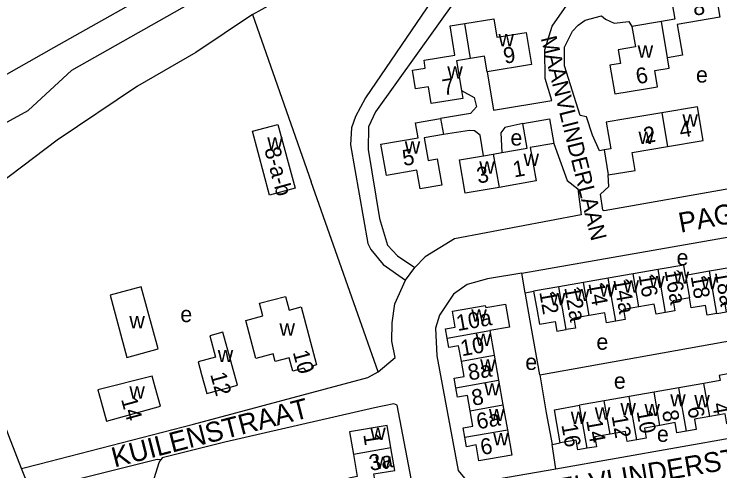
# Model space of a CAD drawing. Extents: x 162883 to 165538, y 383986 to 385172.
# Drawn here: x 163773.3 to 163949.9, y 384629.9 to 384744.4 of the extents above; entities that cross this region are included whole.
import ezdxf

# ---------------------------------------------------------------- set-up
doc = ezdxf.new("R2010")
doc.units = 0
for name, color, linetype in [('BLT_Basislijn', 7, 'Continuous'), ('BLT_Bebouwing', 7, 'Continuous'), ('BLT_Centroide', 7, 'Continuous'), ('BLT_Huisnummer', 7, 'Continuous'), ('BLT_Huisnummer_ tussenligend', 7, 'Continuous'), ('BLT_Huisnummer_reeks', 7, 'Continuous'), ('BLT_Onderverdeling_panden', 7, 'Continuous'), ('BLT_Straatnaam', 7, 'Continuous'), ('BLT_Straatnaam_verkleind', 7, 'Continuous')]:
    doc.layers.add(name, color=color, linetype=linetype)

msp = doc.modelspace()

# ---------------------------------------------------------------- linework, layer by layer
at = {"layer": 'BLT_Basislijn'}
for p, q in [((163864.34, 384654.76), (163847.59, 384702.33)), ((163900.32, 384679.52), (163952.7, 384688.67)), ((163871.23, 384677.72), (163873.56, 384680.91)), ((163901.15, 384674.59), (163900.32, 384679.52)), ((163901.15, 384674.59), (163903.26, 384674.96)), ((163904.83, 384654.01), (163956.75, 384663.31)), ((163908.85, 384630.44), (163960.93, 384639.73)), ((163907.87, 384636.57), (163909.9, 384636.94)), ((163908.85, 384630.44), (163907.87, 384636.57))]:
    msp.add_line(p, q, dxfattribs=at)
for points in [[(163832.96, 384744.27), (163844.99, 384751.02), (164038.65, 384858.43), (164038.88, 384858.81), (164039.72, 384859.01), (164061.27, 384870.58), (164095.24, 384887.32), (164157.3, 384917.02), (164176.04, 384925.47), (164198.09, 384933.36), (164210.88, 384936.92), (164222.14, 384938.13), (164224.6, 384938.13)], [(164063.65, 384861.95), (164053.8, 384860.21), (163989.27, 384824.75), (163955.07, 384806.31), (163947.58, 384801.79), (163891.37, 384764.25), (163884.21, 384756.84), (163877.8, 384747.76), (163861.21, 384723.37), (163858.68, 384718.68), (163857.65, 384715.89), (163857.46, 384711.63), (163861.8, 384686.91), (163862.55, 384685.41), (163865.64, 384681.68), (163871.23, 384677.72)], [(163909.01, 384771.04), (163905.51, 384768.62), (163897.79, 384763.5), (163894.14, 384760.75), (163889.15, 384755.57), (163863.69, 384719.93), (163861.94, 384716.11), (163861.86, 384710.47), (163864.71, 384693.21), (163866.72, 384686.46), (163869.17, 384683.85), (163873.56, 384680.91)], [(163744.77, 384714.19), (163783.24, 384735.97), (163808.01, 384750), (163837.25, 384766.54)], [(163891.64, 384729.92), (163893.2, 384720.33), (163907.82, 384722.7), (163906.17, 384728.2), (163906.04, 384735.41), (163907.92, 384741.34), (163912.16, 384747.42), (163911.34, 384753.42), (163908.22, 384753.15)], [(163750.94, 384709.32), (163762.54, 384712.44), (163776.83, 384720.26), (163787.76, 384730.31), (163822.43, 384750)], [(163832.96, 384744.27), (163818.77, 384734.73), (163804.16, 384726.3), (163784.08, 384712.81), (163766.46, 384699.55), (163764.94, 384697.59), (163763.98, 384695.5), (163763.29, 384693.38), (163762.97, 384690.8), (163763.17, 384688.22), (163763.83, 384685.49), (163768.1, 384671.83), (163760.61, 384669.26)], [(163832.96, 384744.27), (163847.59, 384702.33)], [(163920.88, 384710.36), (163919.72, 384710.1), (163917.95, 384714.03), (163916.51, 384718.66), (163914.9, 384718.93), (163910.97, 384731.44), (163910.94, 384736.09), (163913.02, 384740.08), (163914.38, 384741.63), (163916.13, 384742.84), (163920.23, 384743.91), (163921.27, 384743.08), (163923.41, 384742.13), (163927.04, 384742.49), (163927.86, 384741.28)], [(163885.19, 384725.22), (163888.41, 384723.49), (163888.99, 384721.11), (163887.46, 384719.45), (163879.99, 384718.21)], [(163900.56, 384716.96), (163896.08, 384715.95), (163895.03, 384714.62), (163895.3, 384709.67)], [(163890.73, 384708.88), (163889.86, 384714.01), (163888.46, 384715.15), (163887.24, 384715.24), (163880.69, 384714.19)], [(163908.31, 384711.93), (163911.65, 384702.72), (163914.35, 384700.59), (163915.15, 384694.13), (163883.48, 384688.11), (163876.15, 384683.57), (163873.56, 384680.91)], [(163987.09, 384706.8), (163920.88, 384695.07), (163920.56, 384695.23), (163919.98, 384699.28), (163922.09, 384701.22), (163921.94, 384704.09)], [(163900.32, 384679.52), (163891.75, 384678.05), (163886.6, 384676.62), (163883.17, 384674.24), (163879.67, 384668.92), (163878.68, 384665.73), (163879, 384658.8), (163884.37, 384630.05), (163885.96, 384628.17), (163887.33, 384627.09), (163889.46, 384627.12), (163908.85, 384630.44)], [(163864.34, 384654.76), (163868.62, 384658.37), (163867.8, 384662.46), (163867.86, 384667.08), (163868.53, 384671.82), (163871.23, 384677.72)], [(163904.83, 384654.01), (163902.66, 384666.13), (163901.21, 384674.23), (163901.15, 384674.59)], [(163775.13, 384630.54), (163771.92, 384638.76), (163760.61, 384669.26)], [(163779.42, 384631.65), (163818.14, 384641.66), (163861.78, 384653.34), (163864.34, 384654.76)], [(163904.83, 384654.01), (163906.39, 384644.51), (163907.87, 384636.57)], [(163873.97, 384567.53), (163878.01, 384579.46), (163879.04, 384587.34), (163878.58, 384595.54), (163873.34, 384624.12), (163869.1, 384646.42), (163868.31, 384646.72), (163863.44, 384645.74), (163826.03, 384637.15), (163810.31, 384633.23), (163809.99, 384632.75)], [(163775.13, 384630.54), (163779.42, 384631.65)], [(163809.99, 384632.75), (163809.03, 384632.82), (163777.35, 384624.88)], [(163797.93, 384594.55), (163809.58, 384632.09), (163809.99, 384632.75)], [(163777.35, 384624.88), (163775.13, 384630.54)]]:
    msp.add_lwpolyline(points, dxfattribs=at)
at = {"layer": 'BLT_Bebouwing'}
for p, q in [((163935.25, 384742.54), (163927.86, 384741.28)), ((163901.38, 384739.79), (163902.7, 384731.74)), ((163902.7, 384731.74), (163891.64, 384729.92)), ((163935.31, 384719.62), (163926.36, 384718.11)), ((163873.69, 384717.11), (163879.99, 384718.21)), ((163879.99, 384718.21), (163880.69, 384714.19)), ((163874.34, 384713.38), (163873.69, 384717.11)), ((163865.06, 384711.76), (163874.34, 384713.38)), ((163880.69, 384714.19), (163875.89, 384713.36)), ((163875.89, 384713.36), (163876.88, 384707.68)), ((163866.42, 384703.92), (163865.06, 384711.76)), ((163890.73, 384708.88), (163893.17, 384709.3)), ((163893.17, 384709.3), (163895.3, 384709.67)), ((163922.56, 384710.65), (163920.88, 384710.36)), ((163920.88, 384710.36), (163921.94, 384704.09)), ((163953.65, 384681.07), (163947.25, 384679.96)), ((163928.14, 384679.28), (163921.94, 384678.2)), ((163934.39, 384680.36), (163928.14, 384679.28)), ((163947.25, 384679.96), (163941.24, 384678.92)), ((163921.94, 384678.2), (163915.73, 384677.12)), ((163909.54, 384676.05), (163903.26, 384674.96)), ((163915.73, 384677.12), (163909.54, 384676.05)), ((163892.29, 384665.08), (163893.38, 384658.9)), ((163893.38, 384658.9), (163894.48, 384652.68)), ((163894.48, 384652.68), (163895.58, 384646.46)), ((163939.6, 384650.76), (163933.37, 384649.66)), ((163945.84, 384651.86), (163939.6, 384650.76)), ((163933.37, 384649.66), (163927.15, 384648.57)), ((163920.91, 384647.47), (163914.74, 384646.39)), ((163927.15, 384648.57), (163920.91, 384647.47)), ((163895.58, 384646.46), (163896.68, 384640.25))]:
    msp.add_line(p, q, dxfattribs=at)
for points in [[(163948.74, 384750), (163949.34, 384746.54), (163949.84, 384743.61), (163939.18, 384741.78), (163940.53, 384734.06), (163936.73, 384733.43)], [(163937.6, 384748.97), (163938.61, 384743.12), (163935.25, 384742.54)], [(163886.05, 384741.99), (163893.27, 384743.17), (163894.02, 384738.58), (163901.38, 384739.79)], [(163885.19, 384725.22), (163885.52, 384723.25), (163877.61, 384721.95), (163876.92, 384726.17), (163873.73, 384725.64), (163872.96, 384730.31), (163876.15, 384730.83), (163875.83, 384732.8), (163883.57, 384734.08), (163882.37, 384741.39), (163886.05, 384741.99)], [(163927.86, 384741.28), (163928.73, 384736.19), (163924.43, 384735.45), (163925.02, 384732.02), (163922.3, 384731.55), (163923.54, 384724.36), (163931.24, 384725.68), (163934.25, 384726.19), (163933.56, 384730.23), (163937.17, 384730.86), (163936.73, 384733.43)], [(163891.64, 384729.92), (163891, 384733.81), (163887.49, 384733.24)], [(163887.49, 384733.24), (163883.97, 384732.66), (163885.19, 384725.22)], [(163936.73, 384711.23), (163945.68, 384712.75), (163944.26, 384721.14), (163935.31, 384719.62)], [(163900.56, 384716.96), (163907.23, 384718.11), (163908.31, 384711.93)], [(163926.36, 384718.11), (163921.44, 384717.27), (163922.56, 384710.65)], [(163895.3, 384709.67), (163901.63, 384710.77), (163900.56, 384716.96)], [(163908.31, 384711.93), (163902.43, 384710.92), (163903.87, 384702.57), (163894.61, 384700.96)], [(163921.94, 384704.09), (163928.65, 384705.23), (163927.89, 384709.74), (163936.73, 384711.23)], [(163876.88, 384707.68), (163879.16, 384708.08), (163880.3, 384701.54), (163874.83, 384700.59), (163874.02, 384705.24), (163866.42, 384703.92)], [(163894.61, 384700.96), (163886.15, 384699.5), (163884.7, 384707.84), (163890.73, 384708.88)], [(163941.24, 384678.92), (163940.8, 384681.48), (163934.39, 384680.36)], [(163797.27, 384673.95), (163801.51, 384658.38), (163809.28, 384660.5), (163805.03, 384676.07), (163797.27, 384673.95)], [(163903.26, 384674.96), (163904.12, 384670.03), (163904.7, 384666.68), (163908.66, 384667.37), (163909.09, 384664.94), (163911.4, 384665.34)], [(163942.21, 384673.27), (163938.18, 384672.57), (163938.62, 384670.07), (163936.25, 384669.66)], [(163949.09, 384669.37), (163946.71, 384668.96), (163946.29, 384671.41), (163942.64, 384670.78), (163942.21, 384673.27)], [(163949.09, 384669.37), (163951.47, 384669.78), (163951.05, 384672.23), (163955.06, 384672.92)], [(163881.63, 384663.2), (163881.21, 384665.55), (163883.65, 384665.98), (163882.95, 384669.96), (163891.17, 384671.42), (163891.27, 384670.85), (163896.19, 384671.72), (163897.21, 384665.96), (163892.29, 384665.08)], [(163929.57, 384671.05), (163925.7, 384670.37), (163926.13, 384667.87), (163923.8, 384667.46)], [(163936.25, 384669.66), (163933.88, 384669.25), (163933.45, 384671.72), (163929.57, 384671.05)], [(163917.16, 384668.88), (163913.28, 384668.21), (163913.71, 384665.74), (163911.4, 384665.34)], [(163923.8, 384667.46), (163921.48, 384667.06), (163921.04, 384669.55), (163917.16, 384668.88)], [(163827.85, 384656.24), (163825.53, 384664.68), (163822.21, 384663.77), (163823.67, 384658.48), (163819.29, 384657.28), (163820.15, 384654.12), (163821.48, 384649.3), (163829.18, 384651.42), (163827.85, 384656.24)], [(163885.18, 384657.45), (163884.5, 384661.28), (163882.05, 384660.85), (163881.63, 384663.2)], [(163883.8, 384650.79), (163883.38, 384653.17), (163885.86, 384653.61), (163885.18, 384657.45)], [(163808.61, 384650.96), (163807.86, 384653.71), (163794.24, 384650.22), (163795.05, 384647.26), (163796.36, 384642.43), (163809.93, 384646.13), (163808.61, 384650.96)], [(163952.05, 384652.95), (163951.82, 384654.23), (163949.67, 384653.85), (163949.89, 384652.57), (163945.84, 384651.86)], [(163887.38, 384645.01), (163886.7, 384648.85), (163884.22, 384648.41), (163883.8, 384650.79)], [(163909.9, 384636.94), (163909.04, 384641.86), (163908.44, 384645.27), (163914.74, 384646.39)], [(163886.03, 384638.37), (163885.62, 384640.73), (163888.06, 384641.16), (163887.38, 384645.01)], [(163953.91, 384642.19), (163951.58, 384641.78), (163951.15, 384644.22), (163947.31, 384643.54)], [(163941.5, 384639.93), (163939.1, 384639.51), (163938.65, 384642.04), (163934.83, 384641.36)], [(163947.31, 384643.54), (163943.47, 384642.87), (163943.91, 384640.36), (163941.5, 384639.93)], [(163867.54, 384635.69), (163866.58, 384641.3), (163857.2, 384639.7), (163858.16, 384634.08)], [(163896.68, 384640.25), (163897.8, 384633.93), (163889.57, 384632.48), (163888.87, 384636.44), (163886.45, 384636.01), (163886.03, 384638.37)], [(163934.83, 384641.36), (163931.01, 384640.69), (163931.45, 384638.17), (163929.05, 384637.74)], [(163922.38, 384639.14), (163918.55, 384638.46), (163918.98, 384636.02), (163916.64, 384635.61)], [(163929.05, 384637.74), (163926.65, 384637.32), (163926.21, 384639.82), (163922.38, 384639.14)], [(163916.64, 384635.61), (163914.31, 384635.19), (163913.88, 384637.64), (163909.9, 384636.94)], [(163863.78, 384626.17), (163863.27, 384629.18), (163868.5, 384630.08), (163867.54, 384635.69)], [(163858.16, 384634.08), (163859.11, 384628.54), (163856.99, 384628.17), (163857.52, 384625.1)]]:
    msp.add_lwpolyline(points, dxfattribs=at)
for points in [[(163832.89, 384715.04), (163839.26, 384716.74), (163843.57, 384700.74), (163837.21, 384699.03)], [(163831.26, 384667.63), (163835.54, 384668.77), (163834.7, 384671.93), (163841.21, 384673.67), (163842.13, 384670.23), (163845.08, 384671.02), (163848.94, 384656.53), (163848.09, 384656.3), (163847.95, 384655.5), (163846.31, 384655.05), (163845.79, 384655.68), (163843.01, 384654.92), (163842.1, 384658.27), (163838.57, 384657.33), (163838.06, 384659.26), (163833.79, 384658.12)]]:
    msp.add_lwpolyline(points, close=True, dxfattribs=at)
at = {"layer": 'BLT_Onderverdeling_panden'}
for p, q in [((163887.49, 384733.24), (163886.05, 384741.99)), ((163936.73, 384733.43), (163935.25, 384742.54)), ((163935.31, 384719.62), (163936.73, 384711.23)), ((163893.17, 384709.3), (163894.61, 384700.96)), ((163929.57, 384671.05), (163928.14, 384679.28)), ((163936.25, 384669.66), (163934.39, 384680.36)), ((163949.09, 384669.37), (163947.25, 384679.96)), ((163923.8, 384667.46), (163921.94, 384678.2)), ((163941.24, 384678.92), (163942.21, 384673.27)), ((163911.4, 384665.34), (163909.54, 384676.05)), ((163917.16, 384668.88), (163915.73, 384677.12)), ((163881.63, 384663.2), (163892.29, 384665.08)), ((163885.18, 384657.45), (163893.38, 384658.9)), ((163883.8, 384650.79), (163894.48, 384652.68)), ((163941.5, 384639.93), (163939.6, 384650.76)), ((163947.31, 384643.54), (163945.84, 384651.86)), ((163934.83, 384641.36), (163933.37, 384649.66)), ((163922.38, 384639.14), (163920.91, 384647.47)), ((163929.05, 384637.74), (163927.15, 384648.57)), ((163887.38, 384645.01), (163895.58, 384646.46)), ((163916.64, 384635.61), (163914.74, 384646.39)), ((163886.03, 384638.37), (163896.68, 384640.25)), ((163867.54, 384635.69), (163858.16, 384634.08))]:
    msp.add_line(p, q, dxfattribs=at)

# ---------------------------------------------------------------- texts
at = {"layer": 'BLT_Centroide'}
for s, p in [('w', (163894.47, 384736.28)), ('w', (163929.28, 384733.44)), ('w', (163881.66, 384728.19)), ('e', (163943.87, 384727.22)), ('w', (163940.49, 384716.19)), ('e', (163897.46, 384711.44)), ('w', (163929.49, 384711.84)), ('w', (163836.62, 384710.45)), ('w', (163871.02, 384709.41)), ('w', (163900.73, 384706.33)), ('w', (163889.66, 384704.41)), ('e', (163939.02, 384681.42)), ('w', (163938.3, 384676.81)), ('w', (163925.75, 384674.62)), ('w', (163932.19, 384675.73)), ('w', (163945.17, 384675.41)), ('w', (163913.34, 384672.47)), ('w', (163919.77, 384673.58)), ('w', (163907.33, 384671.41)), ('e', (163814.86, 384667.22)), ('w', (163887.66, 384667.31)), ('w', (163802.12, 384665.65)), ('w', (163839.67, 384663.81)), ('w', (163888.73, 384661.25)), ('e', (163918.96, 384660.3)), ('w', (163824.23, 384657.19)), ('w', (163889.87, 384654.84)), ('e', (163901.17, 384655.24)), ('e', (163923.33, 384650.53)), ('w', (163802.12, 384648.06)), ('w', (163890.93, 384648.84)), ('w', (163937.44, 384646.09)), ('w', (163943.45, 384645.86)), ('w', (163892.07, 384642.41)), ('w', (163918.56, 384642.77)), ('w', (163924.98, 384643.89)), ('w', (163930.98, 384643.67)), ('w', (163912.55, 384641.7)), ('w', (163862.38, 384637.69)), ('e', (163934.1, 384637.22)), ('w', (163893.13, 384636.38)), ('w', (163863.62, 384630.41))]:
    msp.add_text(s, height=4, dxfattribs=at).set_placement(p)
at = {"layer": 'BLT_Huisnummer'}
for s, rotation, p in [('8', 9.7489, (163943.41, 384743.92)), ('9', 9.3254, (163896.01, 384731.92)), ('6', 9.7515, (163929.18, 384726.79)), ('7', 9.333, (163880.72, 384723.97)), ('2', 9.6111, (163931.06, 384711.96)), ('4', 9.6111, (163940.05, 384713.34)), ('5', 9.8813, (163870.76, 384706.29)), ('1', 9.8314, (163898.4, 384703.45)), ('3', 9.8314, (163889.36, 384701.91)), ('16', 279.8546, (163929.46, 384679.06)), ('18a', 279.853, (163948.57, 384679.73)), ('14', 279.852, (163916.95, 384676.93)), ('12', 279.858, (163904.66, 384674.75)), ('10a', 10.0279, (163884.25, 384664.97)), ('10', 284.8889, (163842.98, 384659.67)), ('12', 285.3757, (163822.31, 384654.14)), ('8', 10.0335, (163888.09, 384646.24)), ('14', 285.2481, (163800.01, 384647.9)), ('6', 279.9926, (163941.71, 384645.77)), ('10', 279.9799, (163928.99, 384644.91)), ('16', 279.9841, (163910.19, 384641.49)), ('1', 278.7179, (163860.63, 384639.09)), ('6', 10.0374, (163890.29, 384633.91)), ('3a', 9.7194, (163862.42, 384629.93))]:
    msp.add_text(s, height=4, rotation=rotation, dxfattribs=at).set_placement(p)
at = {"layer": 'BLT_Huisnummer_ tussenligend'}
for s, rotation, p in [('16a', 279.8466, (163935.99, 384680.16)), ('14a', 279.8426, (163923.2, 384677.89)), ('18', 279.6775, (163942.52, 384678.69)), ('12a', 279.8577, (163910.91, 384675.86)), ('10', 10.0275, (163885.3, 384658.66)), ('8a', 10.0346, (163887.17, 384652.58)), ('4', 279.9875, (163947.93, 384646.75)), ('6a', 10.0285, (163889.3, 384640.35)), ('12', 279.9799, (163922.74, 384643.73)), ('8', 279.9926, (163935.37, 384644.87)), ('14', 279.9799, (163916.39, 384642.59))]:
    msp.add_text(s, height=4, rotation=rotation, dxfattribs=at).set_placement(p)
at = {"layer": 'BLT_Huisnummer_reeks'}
msp.add_text('8-a-b', height=4, rotation=285.0209, dxfattribs=at).set_placement((163835.85, 384710.53))
at = {"layer": 'BLT_Straatnaam'}
for s, height, rotation, p in [('PAGELAAN', 5, 10.5729, (163940.01, 384689.58)), ('KUILENSTRAAT', 5, 14.4837, (163798.4, 384630.78)), ('VOGELVLINDERSTRAAT', 4.9999, 9.7924, (163894.91, 384620.46))]:
    msp.add_text(s, height=height, rotation=rotation, dxfattribs=at).set_placement(p)
at = {"layer": 'BLT_Straatnaam_verkleind'}
msp.add_text('MAANVLINDERLAAN', height=3.9999, rotation=284.0141, dxfattribs=at).set_placement((163905.01, 384738.36))

doc.saveas('drawing.dxf')
